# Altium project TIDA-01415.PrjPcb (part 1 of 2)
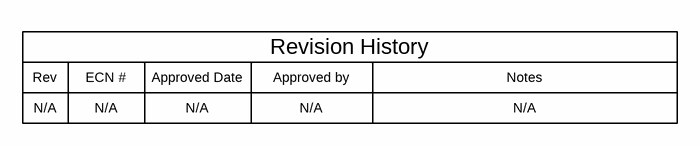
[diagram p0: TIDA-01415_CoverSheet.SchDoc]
CopyrightYear: 2017; EVM Orderable: N/A; PCB_Layout: Kranthi A; PCB_Rev: E1; PRJ_Customer: Public Release; PRJ_Engineer: Surya mishra; PRJ_Number: TIDA-01415; PRJ_Title: High Resolution, high PWM frequency dimmable, color tunable RGBW LED Luminaire; SCH_Rev: E1; TechSupport: http://www.ti.com/support; TID: TIDA-01415
6 sheets, 261 parts. Net scope: flat (ports and power ports of the same name join across sheets).
Board file: TIDA-01415.PcbDoc
Sheets:
  TIDA-01415_CoverSheet.SchDoc
  TIDA-01415_Page1.SchDoc
  TIDA-01415_page3.SchDoc
  TIDA-01415_Page2.SchDoc
  TIDA-01415_page4.SchDoc
  TIDA-01415_EVM_Hardware.SchDoc

## Sheet TIDA-01415_CoverSheet.SchDoc
size 431 x 279 mm; Date: Not shown in title block; ApprovedBy: Not shown in title block; CheckedBy: Not shown in title block; Author: Not shown in title block; CompanyName: Not shown in title block; DrawnBy: Surya Mishra; Engineer: Not shown in title block; Organization: Not shown in title block; Address1: Not shown in title block; Address2: Not shown in title block; Address3: Not shown in title block; Address4: Not shown in title block; DocumentNumber: 1; Revision: Use project parameter SCH_Rev; SheetNumber: 1; SheetTotal: 6; PageSetup: Record=PageOptions¦CenterHorizontal=True¦CenterVertical=True¦PrintScale=1.00¦XCorrection=1.00¦YCorrection=1.00¦PrintKind=0¦BorderSize=5000000¦LeftOffset=0¦BottomOffset=0¦Orientation=2¦PaperLength=1000¦PaperWidth=1000¦Scale=100¦PaperSource=15¦PrintQuality=600¦MediaType=1¦DitherType=10¦PaperKind=Letter¦PrintScaleMode=1

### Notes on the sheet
- Rev
- N/A
- ECN #
- Approved Date
- Approved by
- Revision History
- Notes

## Sheet TIDA-01415_Page1.SchDoc
size 431 x 279 mm; Date: Not shown in title block; ApprovedBy: Not shown in title block; CheckedBy: Not shown in title block; Author: Not shown in title block; CompanyName: Not shown in title block; DrawnBy: Surya Mishra; Engineer: Not shown in title block; Organization: Not shown in title block; Address1: Not shown in title block; Address2: Not shown in title block; Address3: Not shown in title block; Address4: Not shown in title block; DocumentNumber: 1; Revision: Use project parameter SCH_Rev; SheetNumber: 2; SheetTotal: 6; PageSetup: Record=PageOptions¦CenterHorizontal=True¦CenterVertical=True¦PrintScale=1.00¦XCorrection=1.00¦YCorrection=1.00¦PrintKind=0¦BorderSize=5000000¦LeftOffset=0¦BottomOffset=0¦Orientation=2¦PaperLength=1000¦PaperWidth=1000¦Scale=100¦PaperSource=15¦PrintQuality=600¦MediaType=1¦DitherType=10¦PaperKind=Letter¦PrintScaleMode=1
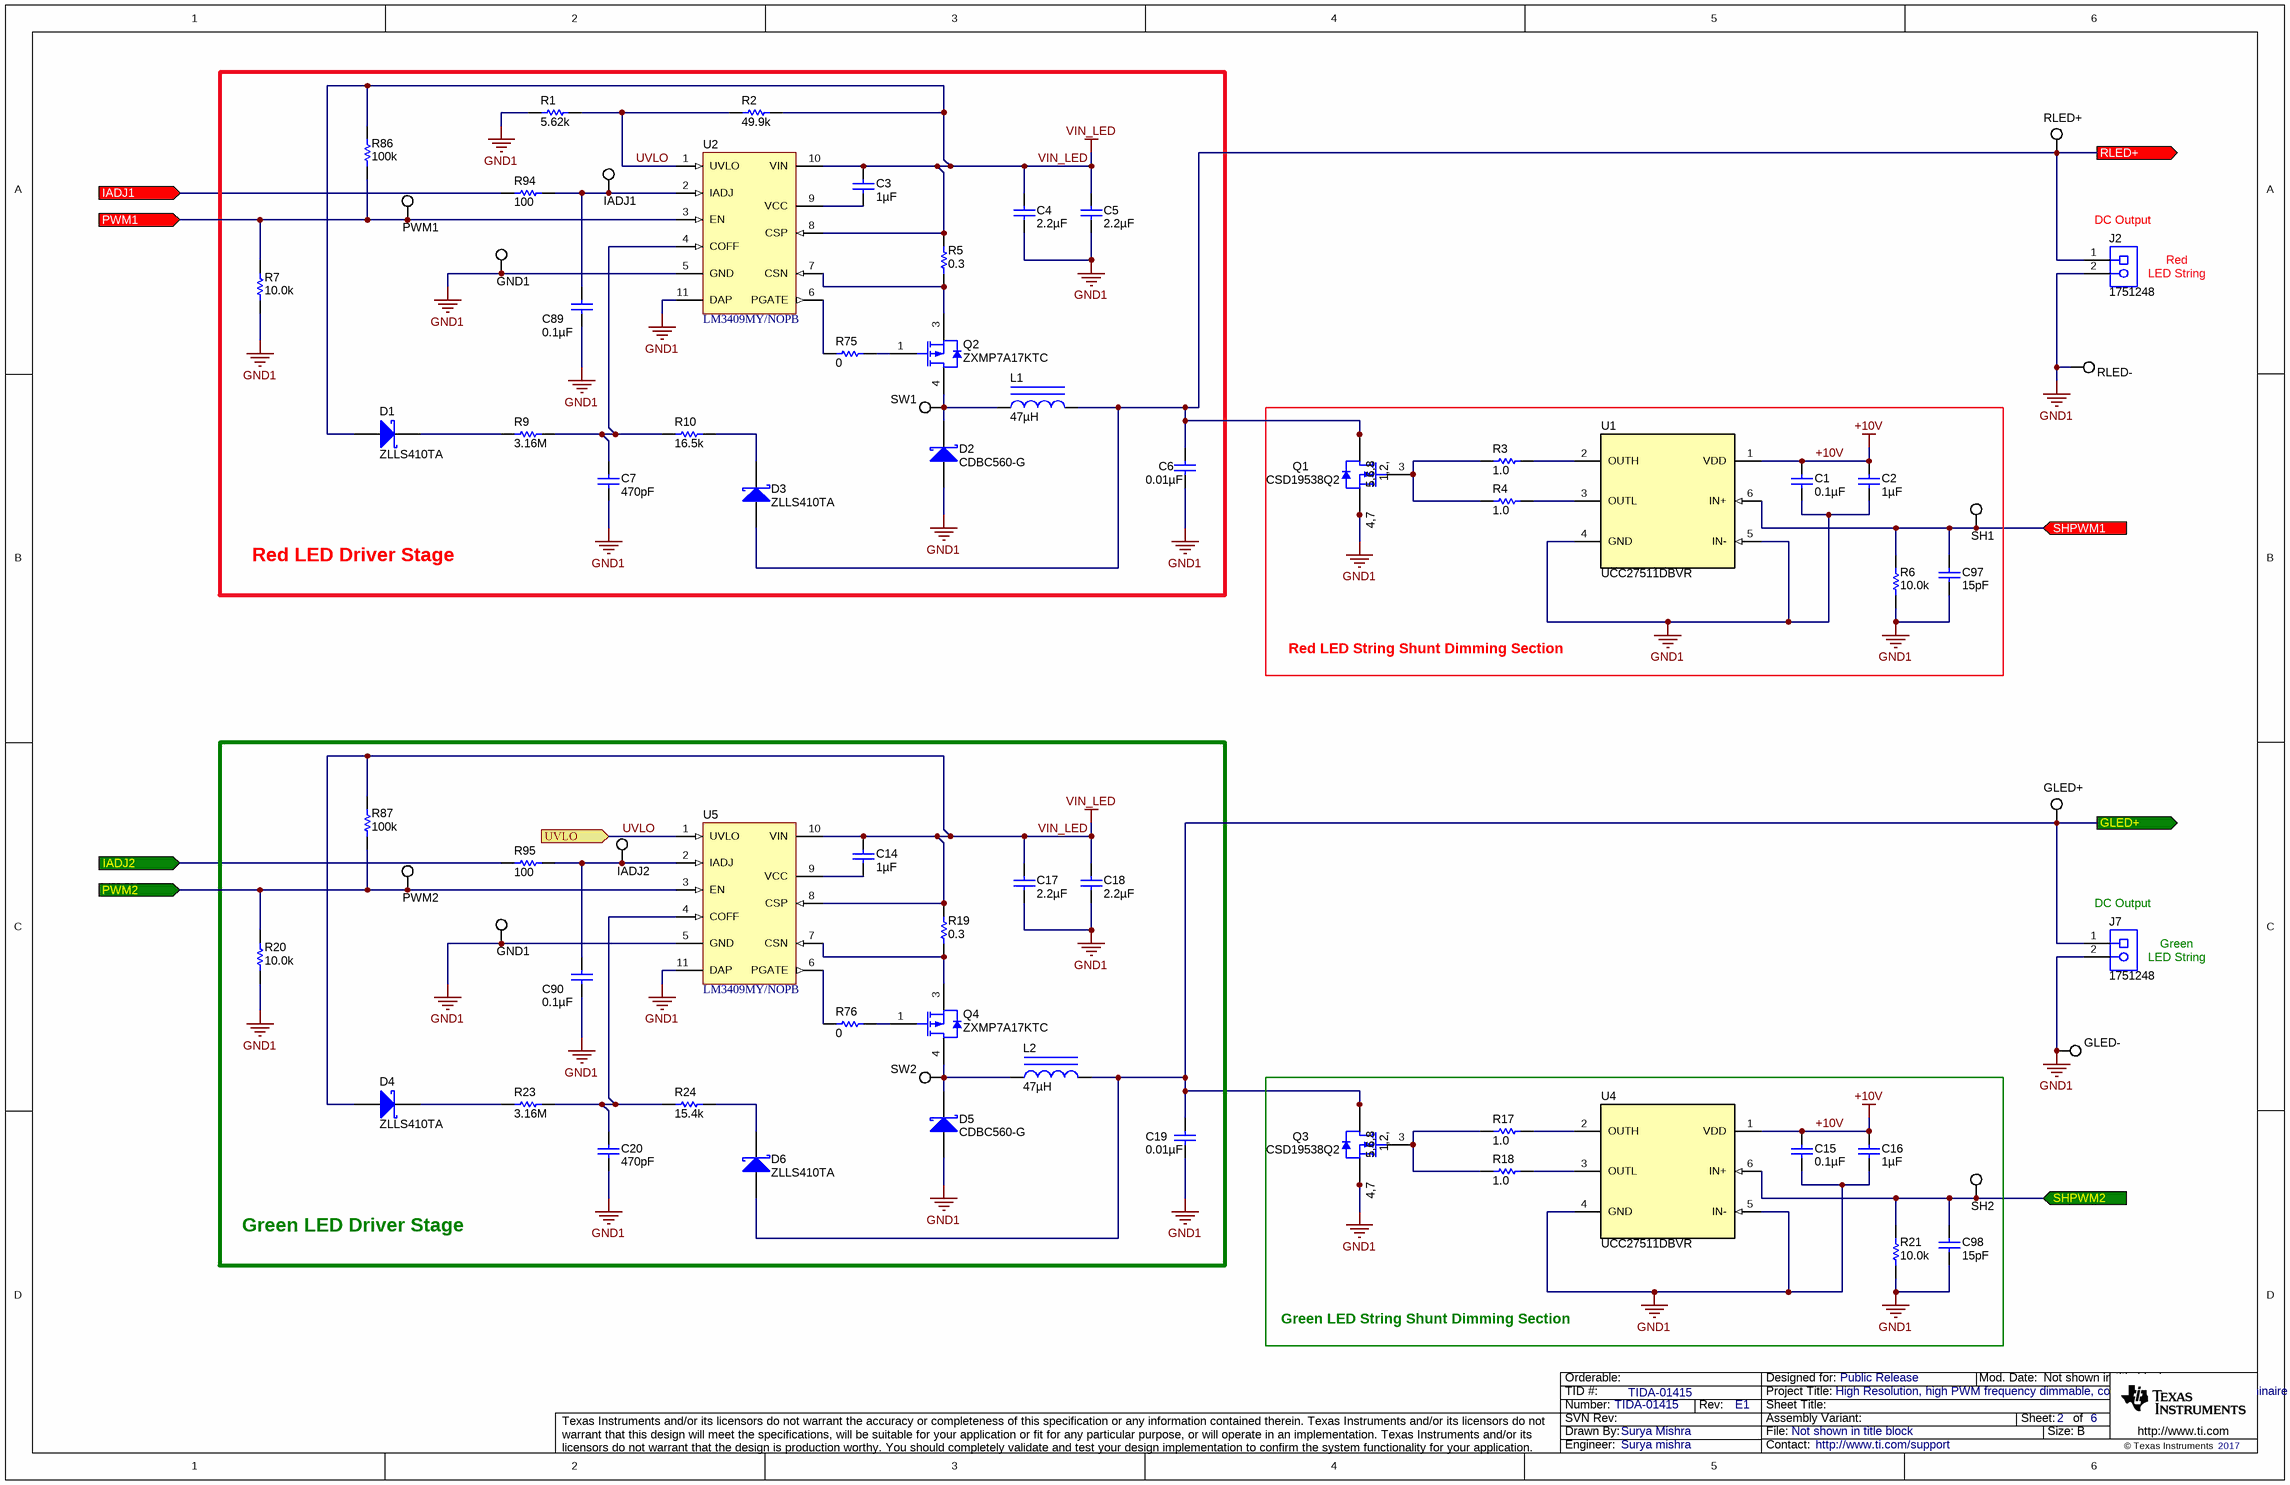
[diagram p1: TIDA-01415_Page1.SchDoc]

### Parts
(Parts that share a designator on the sheet are numbered #1, #2 ... from top to bottom, then left to right.)
C1  ValueDisplayed: 0.1µF  [0805_HV]  (hidden comment: C2012X7R1H104K085AA)
C2  ValueDisplayed: 1µF  [0805_HV]  (hidden comment: C2012X7R1H105K125AB)
C3  ValueDisplayed: 1µF  [0603]  (hidden comment: C1608X7R1C105K080AC)
C4  ValueDisplayed: 2.2µF  [0805_HV]  (hidden comment: C2012X7R1H225K125AC)
C5  ValueDisplayed: 2.2µF  [0805_HV]  (hidden comment: C2012X7R1H225K125AC)
C6  ValueDisplayed: 0.01µF  [0805_HV]  (hidden comment: 885012207092)
C7  ValueDisplayed: 470pF  [0201_033]  (hidden comment: CGA1A2X7R1H471K030BA)
C14  ValueDisplayed: 1µF  [0603]  (hidden comment: C1608X7R1C105K080AC)
C15  ValueDisplayed: 0.1µF  [0805_HV]  (hidden comment: C2012X7R1H104K085AA)
C16  ValueDisplayed: 1µF  [0805_HV]  (hidden comment: C2012X7R1H105K125AB)
C17  ValueDisplayed: 2.2µF  [0805_HV]  (hidden comment: C2012X7R1H225K125AC)
C18  ValueDisplayed: 2.2µF  [0805_HV]  (hidden comment: C2012X7R1H225K125AC)
C19  ValueDisplayed: 0.01µF  [0805_HV]  (hidden comment: 885012207092)
C20  ValueDisplayed: 470pF  [0201_033]  (hidden comment: CGA1A2X7R1H471K030BA)
C89  ValueDisplayed: 0.1µF  [0402]  (hidden comment: C1005X7R1E104M050BB)
C90  ValueDisplayed: 0.1µF  [0402]  (hidden comment: C1005X7R1E104M050BB)
C97  ValueDisplayed: 15pF  [0402]  (hidden comment: 885012005056)
C98  ValueDisplayed: 15pF  [0402]  (hidden comment: 885012005056)
D1  ZLLS410TA  [SOD-323]
D2  CDBC560-G  [SMC]
D3  ZLLS410TA  [SOD-323]
D4  ZLLS410TA  [SOD-323]
D5  CDBC560-G  [SMC]
D6  ZLLS410TA  [SOD-323]
GLED+  5015  [Testpoint_Keystone_Miniature]  (value not drawn)
GLED-  5015  [Testpoint_Keystone_Miniature]  (value not drawn)
GND1#1  5015  [Testpoint_Keystone_Miniature]  (value not drawn)
GND1#2  5015  [Testpoint_Keystone_Miniature]  (value not drawn)
IADJ1  5015  [Testpoint_Keystone_Miniature]  (value not drawn)
IADJ2  5015  [Testpoint_Keystone_Miniature]  (value not drawn)
J2  1751248  [CONN_1751248]
J7  1751248  [CONN_1751248]
L1  ValueDisplayed: 47µH  [WE-PD_1280]  (hidden comment: 744770147)
L2  ValueDisplayed: 47µH  [WE-PD_1280]  (hidden comment: 744770147)
PWM1  5015  [Testpoint_Keystone_Miniature]  (value not drawn)
PWM2  5015  [Testpoint_Keystone_Miniature]  (value not drawn)
Q1  CSD19538Q2  [DQK0006C]
Q2  ZXMP7A17KTC  [DPAK]
Q3  CSD19538Q2  [DQK0006C]
Q4  ZXMP7A17KTC  [DPAK]
R1  ValueDisplayed: 5.62k  [0603]  (hidden comment: CRCW06035K62FKEA)
R2  ValueDisplayed: 49.9k  [0603]  (hidden comment: CRCW060349K9FKEA)
R3  ValueDisplayed: 1.0  [0603]  (hidden comment: CRCW06031R00JNEA)
R4  ValueDisplayed: 1.0  [0603]  (hidden comment: CRCW06031R00JNEA)
R5  ValueDisplayed: 0.3  [2512]  (hidden comment: CSRN2512FKR300)
R6  ValueDisplayed: 10.0k  [0603]  (hidden comment: CRCW060310K0FKEA)
R7  ValueDisplayed: 10.0k  [0603]  (hidden comment: CRCW060310K0FKEA)
R9  ValueDisplayed: 3.16M  [0603]  (hidden comment: CRCW06033M16FKEA)
R10  ValueDisplayed: 16.5k  [0603]  (hidden comment: CRCW060316K5FKEA)
R17  ValueDisplayed: 1.0  [0603]  (hidden comment: CRCW06031R00JNEA)
R18  ValueDisplayed: 1.0  [0603]  (hidden comment: CRCW06031R00JNEA)
R19  ValueDisplayed: 0.3  [2512]  (hidden comment: CSRN2512FKR300)
R20  ValueDisplayed: 10.0k  [0603]  (hidden comment: CRCW060310K0FKEA)
R21  ValueDisplayed: 10.0k  [0603]  (hidden comment: CRCW060310K0FKEA)
R23  ValueDisplayed: 3.16M  [0603]  (hidden comment: CRCW06033M16FKEA)
R24  ValueDisplayed: 15.4k  [0603]  (hidden comment: CRCW060315K4FKEA)
R75  ValueDisplayed: 0  [0603]  (hidden comment: CRCW06030000Z0EA)
R76  ValueDisplayed: 0  [0603]  (hidden comment: CRCW06030000Z0EA)
R86  ValueDisplayed: 100k  [0603]  (hidden comment: CRCW0603100KFKEA)
R87  ValueDisplayed: 100k  [0603]  (hidden comment: CRCW0603100KFKEA)
R94  ValueDisplayed: 100  [0603]  (hidden comment: RC0603FR-07100RL)
R95  ValueDisplayed: 100  [0603]  (hidden comment: RC0603FR-07100RL)
RLED+  5015  [Testpoint_Keystone_Miniature]  (value not drawn)
RLED-  5015  [Testpoint_Keystone_Miniature]  (value not drawn)
SH1  5015  [Testpoint_Keystone_Miniature]  (value not drawn)
SH2  5015  [Testpoint_Keystone_Miniature]  (value not drawn)
SW1  5015  [Testpoint_Keystone_Miniature]  (value not drawn)
SW2  5015  [Testpoint_Keystone_Miniature]  (value not drawn)
U1  UCC27511DBVR  [DBV0006A_N]
U2  LM3409MY/NOPB  [MUC10A_N]
U4  UCC27511DBVR  [DBV0006A_N]
U5  LM3409MY/NOPB  [MUC10A_N]

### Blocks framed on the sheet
Red LED Driver Stage: C3-C7 C89 D1-D3 GND1#1 IADJ1 L1 PWM1 Q2 R1 R2 R5 R7 R9 R10 R75 R86 R94 SW1 U2
Red LED String Shunt Dimming Section: C1 C2 C97 Q1 R3 R4 R6 SH1 U1
Green LED Driver Stage: C14 C17-C20 C90 D4-D6 GND1#2 IADJ2 L2 PWM2 Q4 R19 R20 R23 R24 R76 R87 R95 SW2 U5
Green LED String Shunt Dimming Section: C15 C16 C98 Q3 R17 R18 R21 SH2 U4

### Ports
GLED+ (out), IADJ1 (in), IADJ2 (in), PWM1 (in), PWM2 (in), RLED+ (out), SHPWM1 (in), SHPWM2 (in), UVLO (in)

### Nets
+10V: C1.1 C2.1 C15.1 C16.1 U1.1(VDD) U4.1(VDD)
GND1: C1.2 C2.2 C4.2 C5.2 C6.2 C7.2 C15.2 C16.2 C17.2 C18.2 C19.2 C20.2 C89.1 C90.1 C97.2 C98.2 D2.2(A) D5.2(A) GLED-.1 GND1#1.1 GND1#2.1 J2.2 J7.2 Q1.4(S) Q1.7(S) Q3.4(S) Q3.7(S) R1.1 R6.1 R7.1 R20.1 R21.1 RLED-.1 U1.4(GND) U1.5(IN-) U2.5(GND) U2.11(DAP) U4.4(GND) U4.5(IN-) U5.5(GND) U5.11(DAP)
VIN_LED: C3.1 C4.1 C5.1 C14.1 C17.1 C18.1 D1.2(A) D4.2(A) R2.1 R5.2 R19.2 R86.2 R87.2 U2.8(CSP) U2.10(VIN) U5.8(CSP) U5.10(VIN)
GLED+: C19.1 D6.2(A) GLED+.1 J7.1 L2.2 Q3.1(D) Q3.2(D) Q3.5(D) Q3.6(D) Q3.8(D) ; port GLED+
IADJ1: R94.2 ; port IADJ1
IADJ2: R95.2 ; port IADJ2
PWM1: PWM1.1 R7.2 R86.1 U2.3(EN) ; port PWM1
PWM2: PWM2.1 R20.2 R87.1 U5.3(EN) ; port PWM2
RLED+: C6.1 D3.2(A) J2.1 L1.2 Q1.1(D) Q1.2(D) Q1.5(D) Q1.6(D) Q1.8(D) RLED+.1 ; port RLED+
SHPWM1: C97.1 R6.2 SH1.1 U1.6(IN+) ; port SHPWM1
SHPWM2: C98.1 R21.2 SH2.1 U4.6(IN+) ; port SHPWM2
UVLO: R1.2 R2.2 U2.1(UVLO) U5.1(UVLO) ; port UVLO
NetC3_2: C3.2 U2.9(VCC)
NetC7_1: C7.1 R9.2 R10.1 U2.4(COFF)
NetC14_2: C14.2 U5.9(VCC)
NetC20_1: C20.1 R23.2 R24.1 U5.4(COFF)
NetC89_2: C89.2 IADJ1.1 R94.1 U2.2(IADJ)
NetC90_2: C90.2 IADJ2.1 R95.1 U5.2(IADJ)
NetD1_1: D1.1(K) R9.1
NetD2_1: D2.1(K) L1.1 Q2.4(D) SW1.1
NetD3_1: D3.1(K) R10.2
NetD4_1: D4.1(K) R23.1
NetD5_1: D5.1(K) L2.1 Q4.4(D) SW2.1
NetD6_1: D6.1(K) R24.2
NetQ1_3: Q1.3(G) R3.1 R4.1
NetQ2_1: Q2.1(G) R75.2
NetQ2_3: Q2.3(S) R5.1 U2.7(CSN)
NetQ3_3: Q3.3(G) R17.1 R18.1
NetQ4_1: Q4.1(G) R76.2
NetQ4_3: Q4.3(S) R19.1 U5.7(CSN)
NetR3_2: R3.2 U1.2(OUTH)
NetR4_2: R4.2 U1.3(OUTL)
NetR17_2: R17.2 U4.2(OUTH)
NetR18_2: R18.2 U4.3(OUTL)
NetR75_1: R75.1 U2.6(PGATE)
NetR76_1: R76.1 U5.6(PGATE)

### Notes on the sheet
- (near J2) DC Output
- Red
- (near J2) LED String
- (near J7) DC Output
- (near J7) Green
- (near J7) LED String

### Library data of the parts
C1 C15 = C2012X7R1H104K085AA: CAP, CERM, 0.1 µF, 50 V, +/- 10%, X7R, 0805; Manufacturer: TDK; Polarized: N; CompType: Capacitor; Value: 0.1uF; U/M: EA; Cap_F: 0.0000001; Tolerance_%: 10; ESR_ohm: 0.02619; Value1: 0.02619 ohm; VDC_V: 50; Value2: 50V; IRMS_A: 1.29514; TaMin_C: -55; TaMax_C: 125; Cap_Case: 0805; SizeArea_mm2: 2.5; SizeAreaWB_mm2: 6.75; SizeX_mm: 2; SizeY_mm: 1.25; SizeZ_mm: 1.45; AEC Category: Q200
C2 C16 = C2012X7R1H105K125AB: CAP, CERM, 1 µF, 50 V, +/- 10%, X7R, 0805; Manufacturer: TDK; Polarized: N; CompType: Capacitor; Value: 1uF; U/M: EA; Cap_F: 0.000001; Tolerance_%: 10; ESR_ohm: 0.008782; Value1: 0.008782 ohm; VDC_V: 50; Value2: 50V; IRMS_A: 2.20488; TaMin_C: -55; TaMax_C: 125; Cap_Case: 0805; SizeArea_mm2: 2.5; SizeAreaWB_mm2: 6.75; SizeX_mm: 2; SizeY_mm: 1.25; SizeZ_mm: 1.45; AEC Category: Q200
C3 C14 = C1608X7R1C105K080AC: CAP, CERM, 1 µF, 16 V, +/- 10%, X7R, 0603; Manufacturer: TDK; Polarized: N; CompType: Capacitor; Value: 1uF; U/M: EA; Cap_F: 0.000001; Tolerance_%: 10; ESR_ohm: 0.0057; Value1: 0.0057 ohm; VDC_V: 16; Value2: 16V; TaMin_C: -55; TaMax_C: 125; SizeArea_mm2: 1.28; SizeAreaWB_mm2: 4.68; SizeX_mm: 1.6; SizeY_mm: 0.8; SizeZ_mm: 1; AEC Category: Q200
C4 C5 C17 C18 = C2012X7R1H225K125AC: CAP, CERM, 2.2 µF, 50 V, +/- 10%, X7R, 0805; Manufacturer: TDK; Polarized: N; CompType: Capacitor; Value: 2.2uF; U/M: EA; Cap_F: 0.0000022; Tolerance_%: 10; ESR_ohm: 0.00366; Value1: 0.00366 ohm; VDC_V: 50; Value2: 50V; IRMS_A: 3.41207; TaMin_C: -55; TaMax_C: 125; Cap_Case: 0805; SizeArea_mm2: 2.5; SizeAreaWB_mm2: 6.75; SizeX_mm: 2; SizeY_mm: 1.25; SizeZ_mm: 1.45; AEC Category: Q200
C6 C19 = 885012207092: CAP, CERM, 0.01 µF, 50 V, +/- 10%, X7R, 0805; Manufacturer: Wurth Elektronik; Polarized: N; CompType: Capacitor; Value: 0.01uF; U/M: EA; Cap_F: 0.00000001; Tolerance_%: 10; Value1: Unknown; VDC_V: 50; Value2: 50V; TaMin_C: -55; TaMax_C: 125; Cap_Case: 0805; SizeArea_mm2: 2.5; SizeAreaWB_mm2: 6.75; SizeX_mm: 2; SizeY_mm: 1.25; SizeZ_mm: 1.45; AEC Category: Q200
C7 C20 = CGA1A2X7R1H471K030BA: CAP, CERM, 470 pF, 50 V, +/- 10%, X7R, AEC-Q200 Grade 1, 0201; Manufacturer: TDK; Polarized: N; CompType: Capacitor; Value: 470pF; U/M: EA; Cap_F: 0.00000000047; Tolerance_%: 10; ESR_ohm: 5.54785; Value1: 5.54785 ohm; VDC_V: 50; Value2: 50V; IRMS_A: 0.228855; TaMin_C: -55; TaMax_C: 125; SizeArea_mm2: 0.18; SizeAreaWB_mm2: 2.08; SizeX_mm: 0.6; SizeY_mm: 0.3; SizeZ_mm: 0.33; AEC Category: Q200; AEC Qualified: Y; AEC Grade: 1
C89 C90 = C1005X7R1E104M050BB: CAP, CERM, 0.1 µF, 25 V, +/- 20%, X7R, 0402; Manufacturer: TDK; Polarized: N; CompType: Capacitor; Value: 0.1uF; U/M: EA; Cap_F: 0.0000001; Tolerance_%: 20; Value1: Unknown; VDC_V: 25; Value2: 25V; TaMin_C: -55; TaMax_C: 125; SizeArea_mm2: 0.5; SizeAreaWB_mm2: 3; SizeX_mm: 1; SizeZ_mm: 0.6; AEC Category: Q200
C97 C98 = 885012005056: CAP, CERM, 15 pF, 50 V, +/- 5%, C0G/NP0, 0402; Manufacturer: Wurth Elektronik; Polarized: N; CompType: Capacitor; Value: 15pF; U/M: EA; Cap_F: 0.000000000015; Tolerance_%: 5; Value1: Unknown; VDC_V: 50; Value2: 50V; TaMin_C: -55; TaMax_C: 125; SizeArea_mm2: 0.5; SizeAreaWB_mm2: 3; SizeX_mm: 1; SizeZ_mm: 0.6; AEC Category: Q200
D1 D3 D4 D6 = ZLLS410TA: Diode, Schottky, 10 V, 0.75 A, SOD-323; Manufacturer: Diodes Inc.; U/M: EA; Value: 10V; Value1: 0.75A; Io_A: 0.75; Vr_V: 10; TJmax_C: 150; SizeAreaWB_mm2: 8.695; SizeArea_mm2: 3.645; SizeX_mm: 2.7; SizeY_mm: 1.35; SizeZ_mm: 1; AEC Category: Q101; AEC Qualified: N
D2 D5 = CDBC560-G: Diode, Schottky, 60 V, 5 A, SMC; Manufacturer: Comchip Technology; U/M: EA; Vf_V: 0.75; Value: 60V; Value1: 5A; Value2: 0.75V; Io_A: 5; Vr_V: 60; TJmax_C: 125; SizeAreaWB_mm2: 83.2686; SizeArea_mm2: 50.5686; SizeX_mm: 8.13; SizeY_mm: 6.22; SizeZ_mm: 2.6; AEC Category: Q101
GLED+ GLED- GND1#1 GND1#2 IADJ1 IADJ2 PWM1 PWM2 RLED+ RLED- SH1 SH2 SW1 SW2 = 5015: Test Point, Miniature, SMT; Manufacturer: Keystone; CompType: Test Point Loop
J2 J7 = 1751248: Conn Term Block, 2POS, 3.5mm, TH; Manufacturer: Phoenix Contact; SymbolCreator: a0412235; CompType: Terminal Block
L1 L2 = 744770147: Inductor, Shielded Drum Core, Ferrite, 47 µH, 2.7 A, 0.076 ohm, SMD; Manufacturer: Wurth Elektronik; Value: 47uH; Ind_H: 47.0E-6; Imax_A: 2.7; Irms: 2.7A @ 40C rise; Isat: 3A @ 10% inductance drop; DCR_ohm: 0.076; Value2: 2.7A; SizeAreaWB_mm2: 196; SizeArea_mm2: 144; SizeX_mm: 12; SizeZ_mm: 8; AEC Category: Q200
Q1 Q3 = CSD19538Q2: MOSFET, N-CH, 100 V, 4.5 A, DQK0006C (WSON-6); Manufacturer: Texas Instruments; Alternate Manufacturer: None; U/M: EA; ChType: N; Value: 100V; VdsMax_V: 100; Value1: ? ohm; Value2: ? nC; Vgs_V: 20; IdsMax_A: 4.5; SizeAreaWB_mm2: 9; SizeArea_mm2: 4; SizeX_mm: 2; SizeZ_mm: 0.8; AEC Category: Q101
Q2 Q4 = ZXMP7A17KTC: MOSFET, P-CH, -70 V, -5.7 A, DPAK; Manufacturer: Diodes Inc.; Alternate Manufacturer: None; U/M: EA; ChType: P; Value: -70V; Value1: 0.25 ohm; Rdson45_ohm: 0.25; Value2: 18 nC; QgTyp_nC: 18; Vgs_V: -20; SizeAreaWB_mm2: 101.7114; SizeArea_mm2: 64.8114; SizeX_mm: 9.91; SizeY_mm: 6.54; SizeZ_mm: 2.29; AEC Category: Q101; AEC Qualified: N
R1 = CRCW06035K62FKEA: RES, 5.62 k, 1%, 0.1 W, 0603; Manufacturer: Vishay-Dale; CompType: Resistor; Value: 5.62k; Res_ohm: 5620; Value_Code: 5k62; Tolerance_%: 1; Power_W: 0.1; Value2: 0.1W; VDC_V: 75; TempCo: 100 ppm/C; SizeArea_mm2: 1.28; SizeX_mm: 1.6; SizeY_mm: 0.8; EIA_Code: E96; U/M: EA; AEC Category: Q200
R2 = CRCW060349K9FKEA: RES, 49.9 k, 1%, 0.1 W, 0603; Manufacturer: Vishay-Dale; CompType: Resistor; Value: 49.9k; Res_ohm: 49900; Value_Code: 49k9; Tolerance_%: 1; Power_W: 0.1; Value2: 0.1W; VDC_V: 75; TempCo: 100 ppm/C; SizeArea_mm2: 1.28; SizeX_mm: 1.6; SizeY_mm: 0.8; EIA_Code: E96; U/M: EA; AEC Category: Q200
R3 R4 R17 R18 = CRCW06031R00JNEA: RES, 1.0, 5%, 0.1 W, 0603; Manufacturer: Vishay-Dale; CompType: Resistor; Value: 1.0; Res_ohm: 1; Value_Code: 1R00; Tolerance_%: 5; Power_W: 0.1; Value2: 0.1W; VDC_V: 75; TempCo: 200 ppm/C; SizeArea_mm2: 1.28; SizeX_mm: 1.6; SizeY_mm: 0.8; EIA_Code: E24; U/M: EA; AEC Category: Q200
R5 R19 = CSRN2512FKR300: RES, 0.3, 1%, 2 W, 2512; Manufacturer: Stackpole Electronics Inc; CompType: Resistor; Value: 0.3; Value_Code: R300; Tolerance_%: 1; Power_W: 2; Value2: 2W; TempCo: 200 ppm/C; SizeArea_mm2: 20.16; SizeX_mm: 6.3; SizeY_mm: 3.2; SizeZ_mm: 0.71; EIA_Code: E96; U/M: EA; AEC Category: Q200
R6 R7 R20 R21 = CRCW060310K0FKEA: RES, 10.0 k, 1%, 0.1 W, 0603; Manufacturer: Vishay-Dale; CompType: Resistor; Value: 10.0k; Res_ohm: 10000; Value_Code: 10k0; Tolerance_%: 1; Power_W: 0.1; Value2: 0.1W; VDC_V: 75; TempCo: 100 ppm/C; SizeArea_mm2: 1.28; SizeX_mm: 1.6; SizeY_mm: 0.8; EIA_Code: E96; U/M: EA; AEC Category: Q200
R9 R23 = CRCW06033M16FKEA: RES, 3.16 M, 1%, 0.1 W, 0603; Manufacturer: Vishay-Dale; CompType: Resistor; Value: 3.16Meg; Res_ohm: 3160000; Value_Code: 3M16; Tolerance_%: 1; Power_W: 0.1; Value2: 0.1W; VDC_V: 75; TempCo: 100 ppm/C; SizeArea_mm2: 1.28; SizeX_mm: 1.6; SizeY_mm: 0.8; EIA_Code: E96; U/M: EA; AEC Category: Q200
R10 = CRCW060316K5FKEA: RES, 16.5 k, 1%, 0.1 W, 0603; Manufacturer: Vishay-Dale; CompType: Resistor; Value: 16.5k; Res_ohm: 16500; Value_Code: 16k5; Tolerance_%: 1; Power_W: 0.1; Value2: 0.1W; VDC_V: 75; TempCo: 100 ppm/C; SizeArea_mm2: 1.28; SizeX_mm: 1.6; SizeY_mm: 0.8; EIA_Code: E96; U/M: EA; AEC Category: Q200
R24 = CRCW060315K4FKEA: RES, 15.4 k, 1%, 0.1 W, 0603; Manufacturer: Vishay-Dale; CompType: Resistor; Value: 15.4k; Res_ohm: 15400; Value_Code: 15k4; Tolerance_%: 1; Power_W: 0.1; Value2: 0.1W; VDC_V: 75; TempCo: 100 ppm/C; SizeArea_mm2: 1.28; SizeX_mm: 1.6; SizeY_mm: 0.8; EIA_Code: E96; U/M: EA; AEC Category: Q200
R75 R76 = CRCW06030000Z0EA: RES, 0, 5%, 0.1 W, 0603; Manufacturer: Vishay-Dale; CompType: Resistor; Value: 0; Value_Code: 0000; Tolerance_%: 5; Power_W: 0.1; Value2: 0.1W; VDC_V: 75; TempCo: 200 ppm/C; SizeArea_mm2: 1.28; SizeX_mm: 1.6; SizeY_mm: 0.8; SizeZ_mm: 1; EIA_Code: E24; U/M: EA; AEC Category: Q200
R86 R87 = CRCW0603100KFKEA: RES, 100 k, 1%, 0.1 W, 0603; Manufacturer: Vishay-Dale; CompType: Resistor; Value: 100k; Res_ohm: 100000; Tolerance_%: 1; Power_W: 0.1; Value2: 0.1W; VDC_V: 75; TempCo: 100 ppm/C; SizeArea_mm2: 1.28; SizeX_mm: 1.6; SizeY_mm: 0.8; EIA_Code: E96; U/M: EA; AEC Category: Q200
R94 R95 = RC0603FR-07100RL: RES, 100, 1%, 0.1 W, 0603; Manufacturer: Yageo America; CompType: Resistor; Value: 100; Value_Code: 100R; Tolerance_%: 1; Power_W: 0.1; Value2: 0.1W; VDC_V: 150; TempCo: 200 ppm/C; SizeArea_mm2: 1.28; SizeX_mm: 1.6; SizeY_mm: 0.8; EIA_Code: E96; U/M: EA; AEC Category: Q200
U1 U4 = UCC27511DBVR: Single-Channel High-Speed Low-Side Gate Driver (with 4-A Peak Source and 8-A Peak Sink), DBV0006A (SOT-6); Alternate PartNumber: UCC27511DBVT; Manufacturer: Texas Instruments; SymbolCreator: a0411947; SizeArea_mm2: 8.12; SizeAreaWB_mm2: 14.82; SizeX_mm: 2.8; SizeY_mm: 2.9; SizeZ_mm: 1.45; CompType: IC; U/M: EA
U2 U5 = LM3409MY/NOPB: PFET Buck Controller for High Power LED Drives, 10-pin eMSOP, Pb-Free; Manufacturer: Texas Instruments; PackageTopMarking: ZXTT*SXFB; PowerWise: Y; CompType: MiscPower

## Sheet TIDA-01415_page3.SchDoc
size 431 x 279 mm; Date: Not shown in title block; ApprovedBy: Not shown in title block; CheckedBy: Not shown in title block; Author: Not shown in title block; CompanyName: Not shown in title block; DrawnBy: Surya Mishra; Engineer: Not shown in title block; Organization: Not shown in title block; Address1: Not shown in title block; Address2: Not shown in title block; Address3: Not shown in title block; Address4: Not shown in title block; DocumentNumber: 1; Revision: Use project parameter SCH_Rev; SheetNumber: 4; SheetTotal: 6; PageSetup: Record=PageOptions¦CenterHorizontal=True¦CenterVertical=True¦PrintScale=1.00¦XCorrection=1.00¦YCorrection=1.00¦PrintKind=0¦BorderSize=5000000¦LeftOffset=0¦BottomOffset=0¦Orientation=2¦PaperLength=1000¦PaperWidth=1000¦Scale=100¦PaperSource=15¦PrintQuality=600¦MediaType=1¦DitherType=10¦PaperKind=Letter¦PrintScaleMode=1
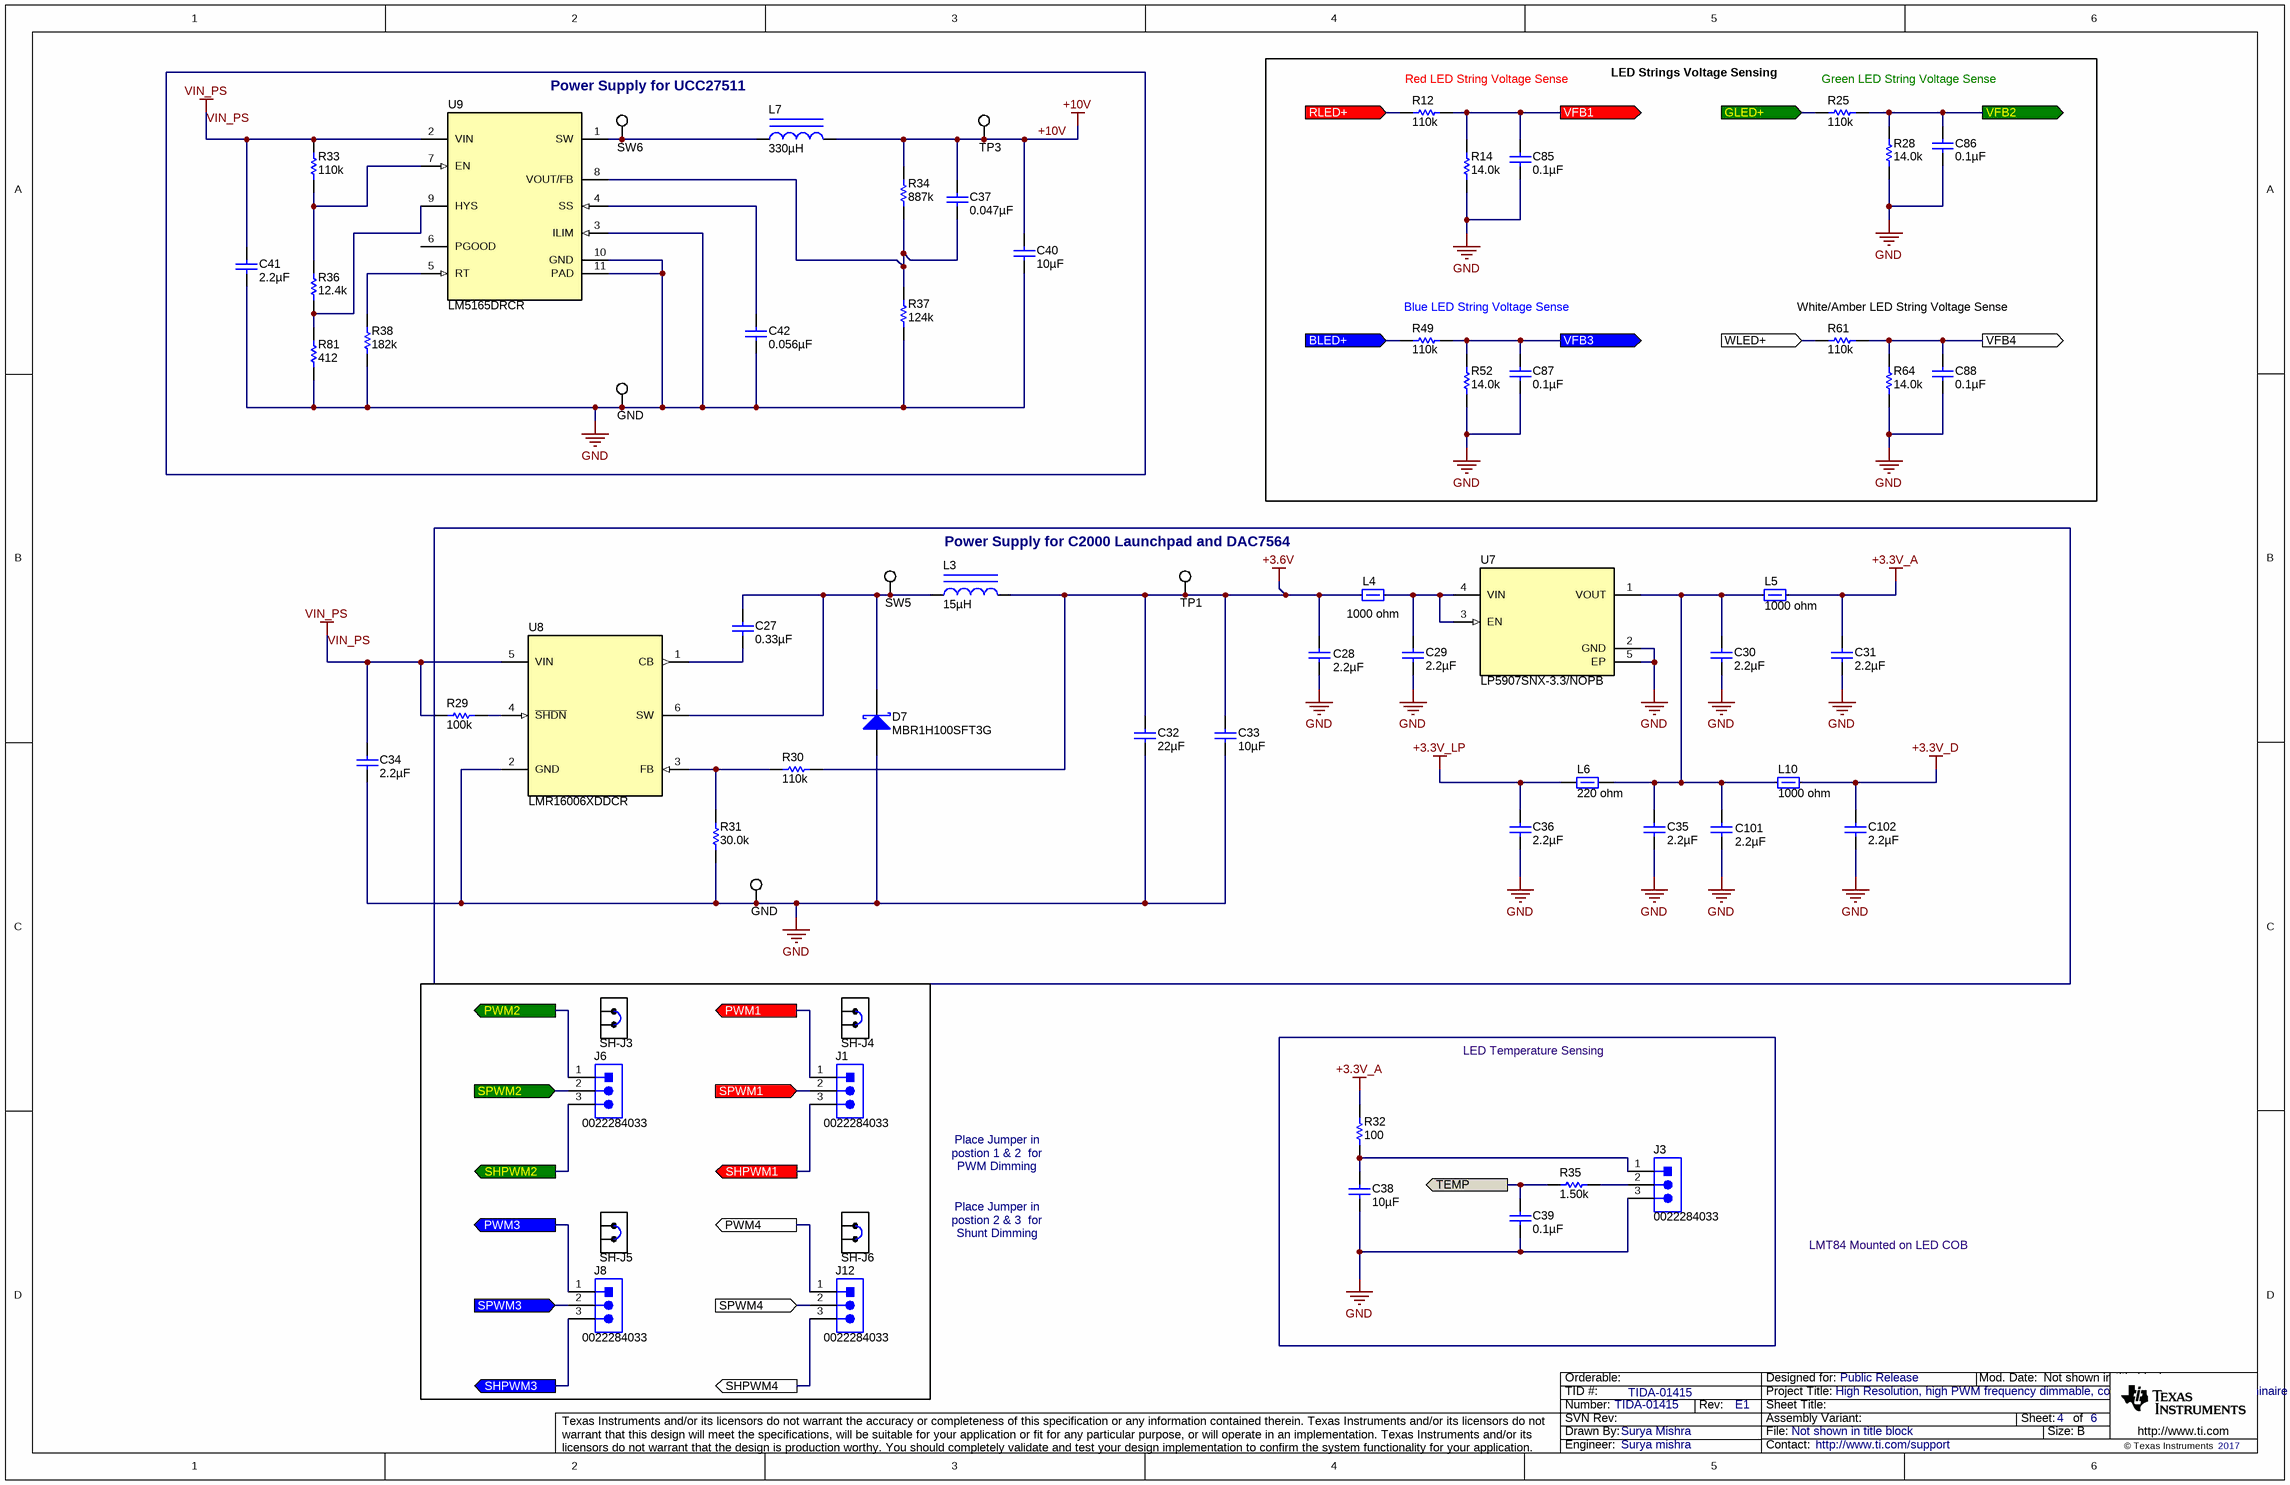
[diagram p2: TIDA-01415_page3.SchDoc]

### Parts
(Parts that share a designator on the sheet are numbered #1, #2 ... from top to bottom, then left to right.)
C27  ValueDisplayed: 0.33µF  [0603]  (hidden comment: C0603C334K4RACTU)
C28  ValueDisplayed: 2.2µF  [0805_HV]  (hidden comment: C2012X7R1C225K125AB)
C29  ValueDisplayed: 2.2µF  [0805_HV]  (hidden comment: C2012X7R1C225K125AB)
C30  ValueDisplayed: 2.2µF  [0805_HV]  (hidden comment: C2012X7R1C225K125AB)
C31  ValueDisplayed: 2.2µF  [0805_HV]  (hidden comment: C2012X7R1C225K125AB)
C32  ValueDisplayed: 22µF  [1206_180]  (hidden comment: GRM31CR61C226KE15L)
C33  ValueDisplayed: 10µF  [0603]  (hidden comment: GRT188C81A106ME13D)
C34  ValueDisplayed: 2.2µF  [0805_HV]  (hidden comment: C2012X7R1H225K125AC)
C35  ValueDisplayed: 2.2µF  [0805_HV]  (hidden comment: C2012X7R1C225K125AB)
C36  ValueDisplayed: 2.2µF  [0805_HV]  (hidden comment: C2012X7R1C225K125AB)
C37  ValueDisplayed: 0.047µF  [0603]  (hidden comment: GCM188R71E473KA37D)
C38  ValueDisplayed: 10µF  [0603]  (hidden comment: GRT188C81A106ME13D)
C39  ValueDisplayed: 0.1µF  [0603]  (hidden comment: GRM188R71E104KA01D)
C40  ValueDisplayed: 10µF  [0805_HV]  (hidden comment: CGA4J1X7S1C106K125AC)
C41  ValueDisplayed: 2.2µF  [0805_HV]  (hidden comment: C2012X7R1H225K125AC)
C42  ValueDisplayed: 0.056µF  [0402]  (hidden comment: GRM155R71C563KA88D)
C85  ValueDisplayed: 0.1µF  [0805_HV]  (hidden comment: C2012X7R1H104K085AA)
C86  ValueDisplayed: 0.1µF  [0805_HV]  (hidden comment: C2012X7R1H104K085AA)
C87  ValueDisplayed: 0.1µF  [0805_HV]  (hidden comment: C2012X7R1H104K085AA)
C88  ValueDisplayed: 0.1µF  [0805_HV]  (hidden comment: C2012X7R1H104K085AA)
C101  ValueDisplayed: 2.2µF  [0805_HV]  (hidden comment: C2012X7R1C225K125AB)
C102  ValueDisplayed: 2.2µF  [0805_HV]  (hidden comment: C2012X7R1C225K125AB)
D7  MBR1H100SFT3G  [SOD-123FL]
GND#1  5015  [Testpoint_Keystone_Miniature]  (value not drawn)
GND#2  5015  [Testpoint_Keystone_Miniature]  (value not drawn)
J1  0022284033  [Molex_0022284033]
J3  0022284033  [Molex_0022284033]
J6  0022284033  [Molex_0022284033]
J8  0022284033  [Molex_0022284033]
J12  0022284033  [Molex_0022284033]
L3  ValueDisplayed: 15µH  [WE-TPC-LH]  (hidden comment: 744053150)
L4  value 1000 ohm  [0603]  (hidden comment: 742792662)
L5  value 1000 ohm  [0603]  (hidden comment: 742792662)
L6  ValueDisplayed: 220 ohm  [0402]  (hidden comment: BLM15AG221SN1D)
L7  ValueDisplayed: 330µH  [SDR0403]  (hidden comment: SDR0403-331KL)
L10  value 1000 ohm  [0603]  (hidden comment: 742792662)
R12  ValueDisplayed: 110k  [0603]  (hidden comment: CRCW0603110KFKEA)
R14  ValueDisplayed: 14.0k  [0603]  (hidden comment: CRCW060314K0FKEA)
R25  ValueDisplayed: 110k  [0603]  (hidden comment: CRCW0603110KFKEA)
R28  ValueDisplayed: 14.0k  [0603]  (hidden comment: CRCW060314K0FKEA)
R29  ValueDisplayed: 100k  [0603]  (hidden comment: CRCW0603100KFKEA)
R30  ValueDisplayed: 110k  [0603]  (hidden comment: CRCW0603110KFKEA)
R31  ValueDisplayed: 30.0k  [0603]  (hidden comment: RC0603FR-0730KL)
R32  ValueDisplayed: 100  [0603]  (hidden comment: RC0603FR-07100RL)
R33  ValueDisplayed: 110k  [0603]  (hidden comment: CRCW0603110KFKEA)
R34  ValueDisplayed: 887k  [0402]  (hidden comment: CRCW0402887KFKED)
R35  ValueDisplayed: 1.50k  [0603]  (hidden comment: RC0603FR-071K5L)
R36  ValueDisplayed: 12.4k  [0603]  (hidden comment: CRCW060312K4FKEA)
R37  ValueDisplayed: 124k  [0402]  (hidden comment: CRCW0402124KFKED)
R38  ValueDisplayed: 182k  [0402]  (hidden comment: CRCW0402182KFKED)
R49  ValueDisplayed: 110k  [0603]  (hidden comment: CRCW0603110KFKEA)
R52  ValueDisplayed: 14.0k  [0603]  (hidden comment: CRCW060314K0FKEA)
R61  ValueDisplayed: 110k  [0603]  (hidden comment: CRCW0603110KFKEA)
R64  ValueDisplayed: 14.0k  [0603]  (hidden comment: CRCW060314K0FKEA)
R81  ValueDisplayed: 412  [1206]  (hidden comment: CRCW1206412RFKEA)
SH-J3  969102-0000-DA  [SNT-100-BK-G]  (value not drawn)
SH-J4  969102-0000-DA  [SNT-100-BK-G]  (value not drawn)
SH-J5  969102-0000-DA  [SNT-100-BK-G]  (value not drawn)
SH-J6  969102-0000-DA  [SNT-100-BK-G]  (value not drawn)
SW5  5015  [Testpoint_Keystone_Miniature]  (value not drawn)
SW6  5015  [Testpoint_Keystone_Miniature]  (value not drawn)
TP1  5015  [Testpoint_Keystone_Miniature]  (value not drawn)
TP3  5015  [Testpoint_Keystone_Miniature]  (value not drawn)
U7  LP5907SNX-3.3/NOPB  [DQN0004A]
U8  LMR16006XDDCR  [DDC0006A_N]
U9  LM5165DRCR  [DRC0010J]

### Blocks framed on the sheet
Power Supply for UCC27511: C37 C40-C42 GND#1 L7 R33 R34 R36-R38 R81 SW6 TP3 U9
Power Supply for C2000 Launchpad and DAC7564: C27-C33 C35 C36 C101 C102 D7 GND#2 L3-L6 L10 R29-R31 SW5 TP1 U7 U8
LED Temperature Sensing: C38 C39 J3 R32 R35

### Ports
BLED+ (in), GLED+ (in), PWM1 (out), PWM2 (out), PWM3 (out), PWM4 (out), RLED+ (in), SHPWM1 (out), SHPWM2 (out), SHPWM3 (out), SHPWM4 (out), SPWM1 (in), SPWM2 (in), SPWM3 (in), SPWM4 (in), TEMP (out), VFB1 (out), VFB2 (out), VFB3 (out), VFB4 (out), WLED+ (in)

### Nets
+3.3V_A: C31.1 L5.2 R32.2
+3.3V_D: C102.1 L10.2
+3.3V_LP: C36.1 L6.2
+3.6V: C28.1 C32.1 C33.1 L3.2 L4.1 R30.2 TP1.1
+10V: C37.1 C40.1 L7.2 R34.2 TP3.1
GND: C28.2 C29.2 C30.2 C31.2 C32.2 C33.2 C34.2 C35.2 C36.2 C38.2 C39.2 C40.2 C41.2 C42.2 C85.1 C86.1 C87.1 C88.1 C101.2 C102.2 D7.2(A) GND#1.1 GND#2.1 J3.3 R14.1 R28.1 R31.1 R37.1 R38.1 R52.1 R64.1 R81.1 U7.2(GND) U7.5(EP) U8.2(GND) U9.3(ILIM) U9.10(GND) U9.11(PAD)
VIN_PS: C34.1 C41.1 R29.2 R33.2 U8.5(VIN) U9.2(VIN)
BLED+: R49.2 ; port BLED+
GLED+: R25.2 ; port GLED+
PWM1: J1.1 ; port PWM1
PWM2: J6.1 ; port PWM2
PWM3: J8.1 ; port PWM3
PWM4: J12.1 ; port PWM4
RLED+: R12.2 ; port RLED+
SHPWM1: J1.3 ; port SHPWM1
SHPWM2: J6.3 ; port SHPWM2
SHPWM3: J8.3 ; port SHPWM3
SHPWM4: J12.3 ; port SHPWM4
SPWM1: J1.2 ; port SPWM1
SPWM2: J6.2 ; port SPWM2
SPWM3: J8.2 ; port SPWM3
SPWM4: J12.2 ; port SPWM4
TEMP: C39.1 R35.1 ; port TEMP
VFB1: C85.2 R12.1 R14.2 ; port VFB1
VFB2: C86.2 R25.1 R28.2 ; port VFB2
VFB3: C87.2 R49.1 R52.2 ; port VFB3
VFB4: C88.2 R61.1 R64.2 ; port VFB4
WLED+: R61.2 ; port WLED+
NetC27_1: C27.1 D7.1(K) L3.1 SW5.1 U8.6(SW)
NetC27_2: C27.2 U8.1(CB)
NetC29_1: C29.1 L4.2 U7.3(EN) U7.4(VIN)
NetC30_1: C30.1 C35.1 C101.1 L5.1 L6.1 L10.1 U7.1(VOUT)
NetC37_2: C37.2 R34.1 R37.2 U9.8(VOUT/FB)
NetC38_1: C38.1 J3.1 R32.1
NetC42_1: C42.1 U9.4(SS)
NetJ3_2: J3.2 R35.2
NetL7_1: L7.1 SW6.1 U9.1(SW)
NetR29_1: R29.1 U8.4(~{SHDN})
NetR30_1: R30.1 R31.2 U8.3(FB)
NetR33_1: R33.1 R36.2 U9.7(EN)
NetR36_1: R36.1 R81.2 U9.9(HYS)
NetR38_2: R38.2 U9.5(RT)

Not connected (* = marked no-connect by the designer): U9 6(PGOOD)

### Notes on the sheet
- (near R12) Red LED String Voltage Sense
- LED Strings Voltage Sensing
- (near R25) Green LED String Voltage Sense
- (near R49) Blue LED String Voltage Sense
- (near R61) White/Amber LED String Voltage Sense
- Place Jumper in postion 1 & 2  for PWM Dimming
- LMT84 Mounted on LED COB
- Place Jumper in postion 2 & 3  for Shunt Dimming

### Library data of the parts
C27 = C0603C334K4RACTU: CAP, CERM, 0.33 µF, 16 V, +/- 10%, X7R, 0603; Manufacturer: Kemet; Polarized: N; CompType: Capacitor; Value: 0.33uF; U/M: EA; Cap_F: 0.00000033; Tolerance_%: 10; Value1: Unknown; VDC_V: 16; Value2: 16V; TaMin_C: -55; TaMax_C: 125; SizeArea_mm2: 1.28; SizeAreaWB_mm2: 4.68; SizeX_mm: 1.6; SizeY_mm: 0.8; SizeZ_mm: 1; AEC Category: Q200
C28-C31 C35 C36 C101 C102 = C2012X7R1C225K125AB: CAP, CERM, 2.2 µF, 16 V, +/- 10%, X7R, 0805; Manufacturer: TDK; Polarized: N; CompType: Capacitor; Value: 2.2uF; U/M: EA; Cap_F: 0.0000022; Tolerance_%: 10; ESR_ohm: 0.0049; Value1: 0.0049 ohm; VDC_V: 16; Value2: 16V; TaMin_C: -55; TaMax_C: 125; Cap_Case: 0805; SizeArea_mm2: 2.5; SizeAreaWB_mm2: 6.75; SizeX_mm: 2; SizeY_mm: 1.25; SizeZ_mm: 1.45; AEC Category: Q200
C32 = GRM31CR61C226KE15L: CAP, CERM, 22 µF, 16 V, +/- 10%, X5R, 1206; Manufacturer: MuRata; Polarized: N; CompType: Capacitor; Value: 22uF; U/M: EA; Cap_F: 0.000022; Tolerance_%: 10; Value1: Unknown; VDC_V: 16; Value2: 16V; TaMin_C: -55; TaMax_C: 85; Cap_Case: 1206; SizeArea_mm2: 5.12; SizeAreaWB_mm2: 10.92; SizeX_mm: 3.2; SizeY_mm: 1.6; SizeZ_mm: 1.8; AEC Category: Q200
C33 C38 = GRT188C81A106ME13D: CAP, CERM, 10 µF, 10 V, +/- 20%, X6S, AEC-Q200 Grade 2, 0603; Manufacturer: MuRata; Polarized: N; CompType: Capacitor; Value: 10uF; U/M: EA; Cap_F: 0.00001; Tolerance_%: 20; Value1: Unknown; VDC_V: 10; Value2: 10V; TaMin_C: -55; TaMax_C: 105; SizeArea_mm2: 1.28; SizeAreaWB_mm2: 4.68; SizeX_mm: 1.6; SizeY_mm: 0.8; SizeZ_mm: 1; AEC Category: Q200; AEC Qualified: Y; AEC Grade: 2
C34 C41 = C2012X7R1H225K125AC: as C4 on sheet TIDA-01415_Page1
C37 = GCM188R71E473KA37D: CAP, CERM, 0.047 µF, 25 V, +/- 10%, X7R, AEC-Q200 Grade 1, 0603; Manufacturer: MuRata; Polarized: N; CompType: Capacitor; Value: 0.047uF; U/M: EA; Cap_F: 0.000000047; Tolerance_%: 10; Value1: Unknown; VDC_V: 25; Value2: 25V; TaMin_C: -55; TaMax_C: 125; SizeArea_mm2: 1.28; SizeAreaWB_mm2: 4.68; SizeX_mm: 1.6; SizeY_mm: 0.8; SizeZ_mm: 1; AEC Category: Q200; AEC Qualified: Y
C39 = GRM188R71E104KA01D: CAP, CERM, 0.1 µF, 25 V, +/- 10%, X7R, 0603; Manufacturer: MuRata; Polarized: N; CompType: Capacitor; Value: 0.1uF; U/M: EA; Cap_F: 0.0000001; Tolerance_%: 10; Value1: Unknown; VDC_V: 25; Value2: 25V; TaMin_C: -55; TaMax_C: 125; SizeArea_mm2: 1.28; SizeAreaWB_mm2: 4.68; SizeX_mm: 1.6; SizeY_mm: 0.8; SizeZ_mm: 1; AEC Category: Q200
C40 = CGA4J1X7S1C106K125AC: CAP, CERM, 10 µF, 16 V, +/- 10%, X7S, AEC-Q200 Grade 1, 0805; Manufacturer: TDK; Polarized: N; CompType: Capacitor; Value: 10uF; U/M: EA; Cap_F: 0.00001; Tolerance_%: 10; Value1: Unknown; VDC_V: 16; Value2: 16V; TaMin_C: -55; TaMax_C: 125; Cap_Case: 0805; SizeArea_mm2: 2.5; SizeAreaWB_mm2: 6.75; SizeX_mm: 2; SizeY_mm: 1.25; SizeZ_mm: 1.45; AEC Category: Q200; AEC Qualified: Y; AEC Grade: 1
C42 = GRM155R71C563KA88D: CAP, CERM, 0.056 µF, 16 V, +/- 10%, X7R, 0402; Manufacturer: MuRata; Polarized: N; CompType: Capacitor; Value: 0.056uF; U/M: EA; Cap_F: 0.000000056; Tolerance_%: 10; Value1: Unknown; VDC_V: 16; Value2: 16V; TaMin_C: -55; TaMax_C: 125; SizeArea_mm2: 0.5; SizeAreaWB_mm2: 3; SizeX_mm: 1; SizeZ_mm: 0.6; AEC Category: Q200
C85-C88 = C2012X7R1H104K085AA: as C1 on sheet TIDA-01415_Page1
D7 = MBR1H100SFT3G: Diode, Schottky, 100 V, 1 A, SOD-123FL; Manufacturer: ON Semiconductor; U/M: EA; Vf_V: 0.76; Value: 100V; Value1: 1A; Value2: 0.76V; Io_A: 1; Vr_V: 100; TJmax_C: 175; RJC_CperW: 85; SizeAreaWB_mm2: 12.19; SizeArea_mm2: 5.94; SizeX_mm: 3.6; SizeY_mm: 1.65; SizeZ_mm: 0.98; AEC Category: Q101
GND#1 GND#2 SW5 SW6 TP1 TP3 = 5015: as GLED+ on sheet TIDA-01415_Page1
J1 J3 J6 J8 J12 = 0022284033: Header, 2.54mm, 3x1, Tin, TH; Manufacturer: Molex; SymbolCreator: a0799628; Pitch_mm: 2.54; Gender: Male; Shrouded: N; Row_Count: 1; Current_A: 4; Voltage_V: 250; Cert_UL: Y
L3 = 744053150: Inductor, Shielded Drum Core, Ferrite, 15 µH, 1.15 A, 0.07 ohm, SMD; Manufacturer: Wurth Elektronik; Value: 15uH; Ind_H: 15.0E-6; Imax_A: 1.15; Irms: 1.38A @ 30C rise; Isat: 1.15A @ 35% inductance drop; DCR_ohm: 0.07; Value2: 1.15A; SizeAreaWB_mm2: 60.84; SizeArea_mm2: 33.64; SizeX_mm: 5.8; SizeZ_mm: 2.8; AEC Category: Q200
L4 L5 L10 = 742792662: Ferrite Bead, 1000 ohm @ 100 MHz, 0.6 A, 0603; Manufacturer: Wurth Elektronik; Imax_A: 0.6; DCR_ohm: 0.3; Value1: 0.3 ohm; Value2: 0.6A; ZTyp@100MHz_Ohm: 1000
L6 = BLM15AG221SN1D: Ferrite Bead, 220 ohm @ 100 MHz, 0.45 A, 0402; Manufacturer: MuRata; Value: 220 ohm; Imax_A: 0.45; DCR_ohm: 0.29; Value1: 0.29 ohm; Value2: 0.45A; SizeAreaWB_mm2: 3; SizeArea_mm2: 0.5; SizeX_mm: 1; SizeZ_mm: 0.6; ZTyp@100MHz_Ohm: 220
L7 = SDR0403-331KL: Inductor, Drum Core, Ferrite, 330 µH, 0.17 A, 6 ohm, SMD; Manufacturer: Bourns; Value: 330uH; Ind_H: 330.0E-6; Imax_A: 0.17; Irms: 0.17A @ 40C rise; Isat: 0.25A @ 10% inductance drop; DCR_ohm: 6; Value1: 6 ohm; Value2: 0.17A; SizeAreaWB_mm2: 27.5; SizeArea_mm2: 18; SizeX_mm: 4.5; SizeY_mm: 4; SizeZ_mm: 3.2; AEC Category: Q200
R12 R25 R30 R33 R49 R61 = CRCW0603110KFKEA: RES, 110 k, 1%, 0.1 W, 0603; Manufacturer: Vishay-Dale; CompType: Resistor; Value: 110k; Res_ohm: 110000; Tolerance_%: 1; Power_W: 0.1; Value2: 0.1W; VDC_V: 75; TempCo: 100 ppm/C; SizeArea_mm2: 1.28; SizeX_mm: 1.6; SizeY_mm: 0.8; EIA_Code: E96; U/M: EA; AEC Category: Q200
R14 R28 R52 R64 = CRCW060314K0FKEA: RES, 14.0 k, 1%, 0.1 W, 0603; Manufacturer: Vishay-Dale; CompType: Resistor; Value: 14.0k; Res_ohm: 14000; Value_Code: 14k0; Tolerance_%: 1; Power_W: 0.1; Value2: 0.1W; VDC_V: 75; TempCo: 100 ppm/C; SizeArea_mm2: 1.28; SizeX_mm: 1.6; SizeY_mm: 0.8; EIA_Code: E96; U/M: EA; AEC Category: Q200
R29 = CRCW0603100KFKEA: as R86 on sheet TIDA-01415_Page1
R31 = RC0603FR-0730KL: RES, 30.0 k, 1%, 0.1 W, 0603; Manufacturer: Yageo America; CompType: Resistor; Value: 30.0k; Res_ohm: 30000; Value_Code: 30k0; Tolerance_%: 1; Power_W: 0.1; Value2: 0.1W; VDC_V: 150; TempCo: 200 ppm/C; SizeArea_mm2: 1.28; SizeX_mm: 1.6; SizeY_mm: 0.8; U/M: EA; AEC Category: Q200
R32 = RC0603FR-07100RL: as R94 on sheet TIDA-01415_Page1
R34 = CRCW0402887KFKED: RES, 887 k, 1%, 0.063 W, 0402; Manufacturer: Vishay-Dale; CompType: Resistor; Value: 887k; Res_ohm: 887000; Tolerance_%: 1; Power_W: 0.063; Value2: 0.063W; VDC_V: 50; TempCo: 100 ppm/C; SizeArea_mm2: 0.5; SizeZ_mm: 0.6; EIA_Code: E96; U/M: EA; AEC Category: Q200
R35 = RC0603FR-071K5L: RES, 1.50 k, 1%, 0.1 W, 0603; Manufacturer: Yageo America; CompType: Resistor; Value: 1.50k; Res_ohm: 1500; Value_Code: 1k50; Tolerance_%: 1; Power_W: 0.1; Value2: 0.1W; VDC_V: 150; TempCo: 200 ppm/C; SizeArea_mm2: 1.28; SizeX_mm: 1.6; SizeY_mm: 0.8; EIA_Code: E96; U/M: EA; AEC Category: Q200
R36 = CRCW060312K4FKEA: RES, 12.4 k, 1%, 0.1 W, 0603; Manufacturer: Vishay-Dale; CompType: Resistor; Value: 12.4k; Res_ohm: 12400; Value_Code: 12k4; Tolerance_%: 1; Power_W: 0.1; Value2: 0.1W; VDC_V: 75; TempCo: 100 ppm/C; SizeArea_mm2: 1.28; SizeX_mm: 1.6; SizeY_mm: 0.8; EIA_Code: E96; U/M: EA; AEC Category: Q200
R37 = CRCW0402124KFKED: RES, 124 k, 1%, 0.063 W, 0402; Manufacturer: Vishay-Dale; CompType: Resistor; Value: 124k; Res_ohm: 124000; Tolerance_%: 1; Power_W: 0.063; Value2: 0.063W; VDC_V: 50; TempCo: 100 ppm/C; SizeArea_mm2: 0.5; SizeZ_mm: 0.6; EIA_Code: E96; U/M: EA; AEC Category: Q200
R38 = CRCW0402182KFKED: RES, 182 k, 1%, 0.063 W, 0402; Manufacturer: Vishay-Dale; CompType: Resistor; Value: 182k; Res_ohm: 182000; Tolerance_%: 1; Power_W: 0.063; Value2: 0.063W; VDC_V: 50; TempCo: 100 ppm/C; SizeArea_mm2: 0.5; SizeZ_mm: 0.6; EIA_Code: E96; U/M: EA; AEC Category: Q200
R81 = CRCW1206412RFKEA: RES, 412, 1%, 0.25 W, 1206; Manufacturer: Vishay-Dale; CompType: Resistor; Value: 412; Value_Code: 412R; Tolerance_%: 1; Power_W: 0.25; Value2: 0.25W; VDC_V: 200; TempCo: 100 ppm/C; SizeArea_mm2: 5.12; SizeX_mm: 3.2; SizeY_mm: 1.6; SizeZ_mm: 1.35; EIA_Code: E96; U/M: EA; AEC Category: Q200
SH-J3-SH-J6 = 969102-0000-DA: Shunt, 100mil, Gold plated, Black; Manufacturer: 3M; Alternate Manufacturer: Samtec; Value: 1x2; Note: You can "mate" this to a header by matching the designator.  i.e. use SH-J3 for header J3
U7 = LP5907SNX-3.3/NOPB: 250-mA Ultra-Low-Noise, Low-IQ LDO, DQN0004A (X2SON-4); Manufacturer: Texas Instruments; SymbolCreator: Altium; SizeArea_mm2: 1; SizeAreaWB_mm2: 4; SizeZ_mm: 0.4; CompType: IC; U/M: EA
U8 = LMR16006XDDCR: Wide Input Voltage Range Buck Regulator with High Efficiency Sleep Mode, DDC0006A (SOT-6); Alternate PartNumber: LMR16006XDDCT; Manufacturer: Texas Instruments; SymbolCreator: x0208326; SizeArea_mm2: 4.8675; SizeAreaWB_mm2: 10.4675; SizeX_mm: 1.65; SizeY_mm: 2.95; SizeZ_mm: 0.87; CompType: IC; U/M: EA
U9 = LM5165DRCR: 3V-65V, 150mA Synchronous Buck Converter With Ultra-Low IQ, DRC0010J (VSON-10); Alternate PartNumber: LM5165DRCT; Manufacturer: Texas Instruments; SymbolCreator: Altium; SizeArea_mm2: 9; SizeAreaWB_mm2: 16; SizeX_mm: 3; SizeZ_mm: 1; CompType: IC; U/M: EA

## Sheet TIDA-01415_Page2.SchDoc
size 431 x 279 mm; Date: Not shown in title block; ApprovedBy: Not shown in title block; CheckedBy: Not shown in title block; Author: Not shown in title block; CompanyName: Not shown in title block; Engineer: Not shown in title block; Organization: Not shown in title block; Address1: Not shown in title block; Address2: Not shown in title block; Address3: Not shown in title block; Address4: Not shown in title block; DocumentNumber: 1; Revision: Use project parameter SCH_Rev; SheetNumber: 3; SheetTotal: 6; PageSetup: Record=PageOptions¦CenterHorizontal=True¦CenterVertical=True¦PrintScale=1.00¦XCorrection=1.00¦YCorrection=1.00¦PrintKind=0¦BorderSize=5000000¦LeftOffset=0¦BottomOffset=0¦Orientation=2¦PaperLength=1000¦PaperWidth=1000¦Scale=100¦PaperSource=15¦PrintQuality=600¦MediaType=1¦DitherType=10¦PaperKind=Letter¦PrintScaleMode=1
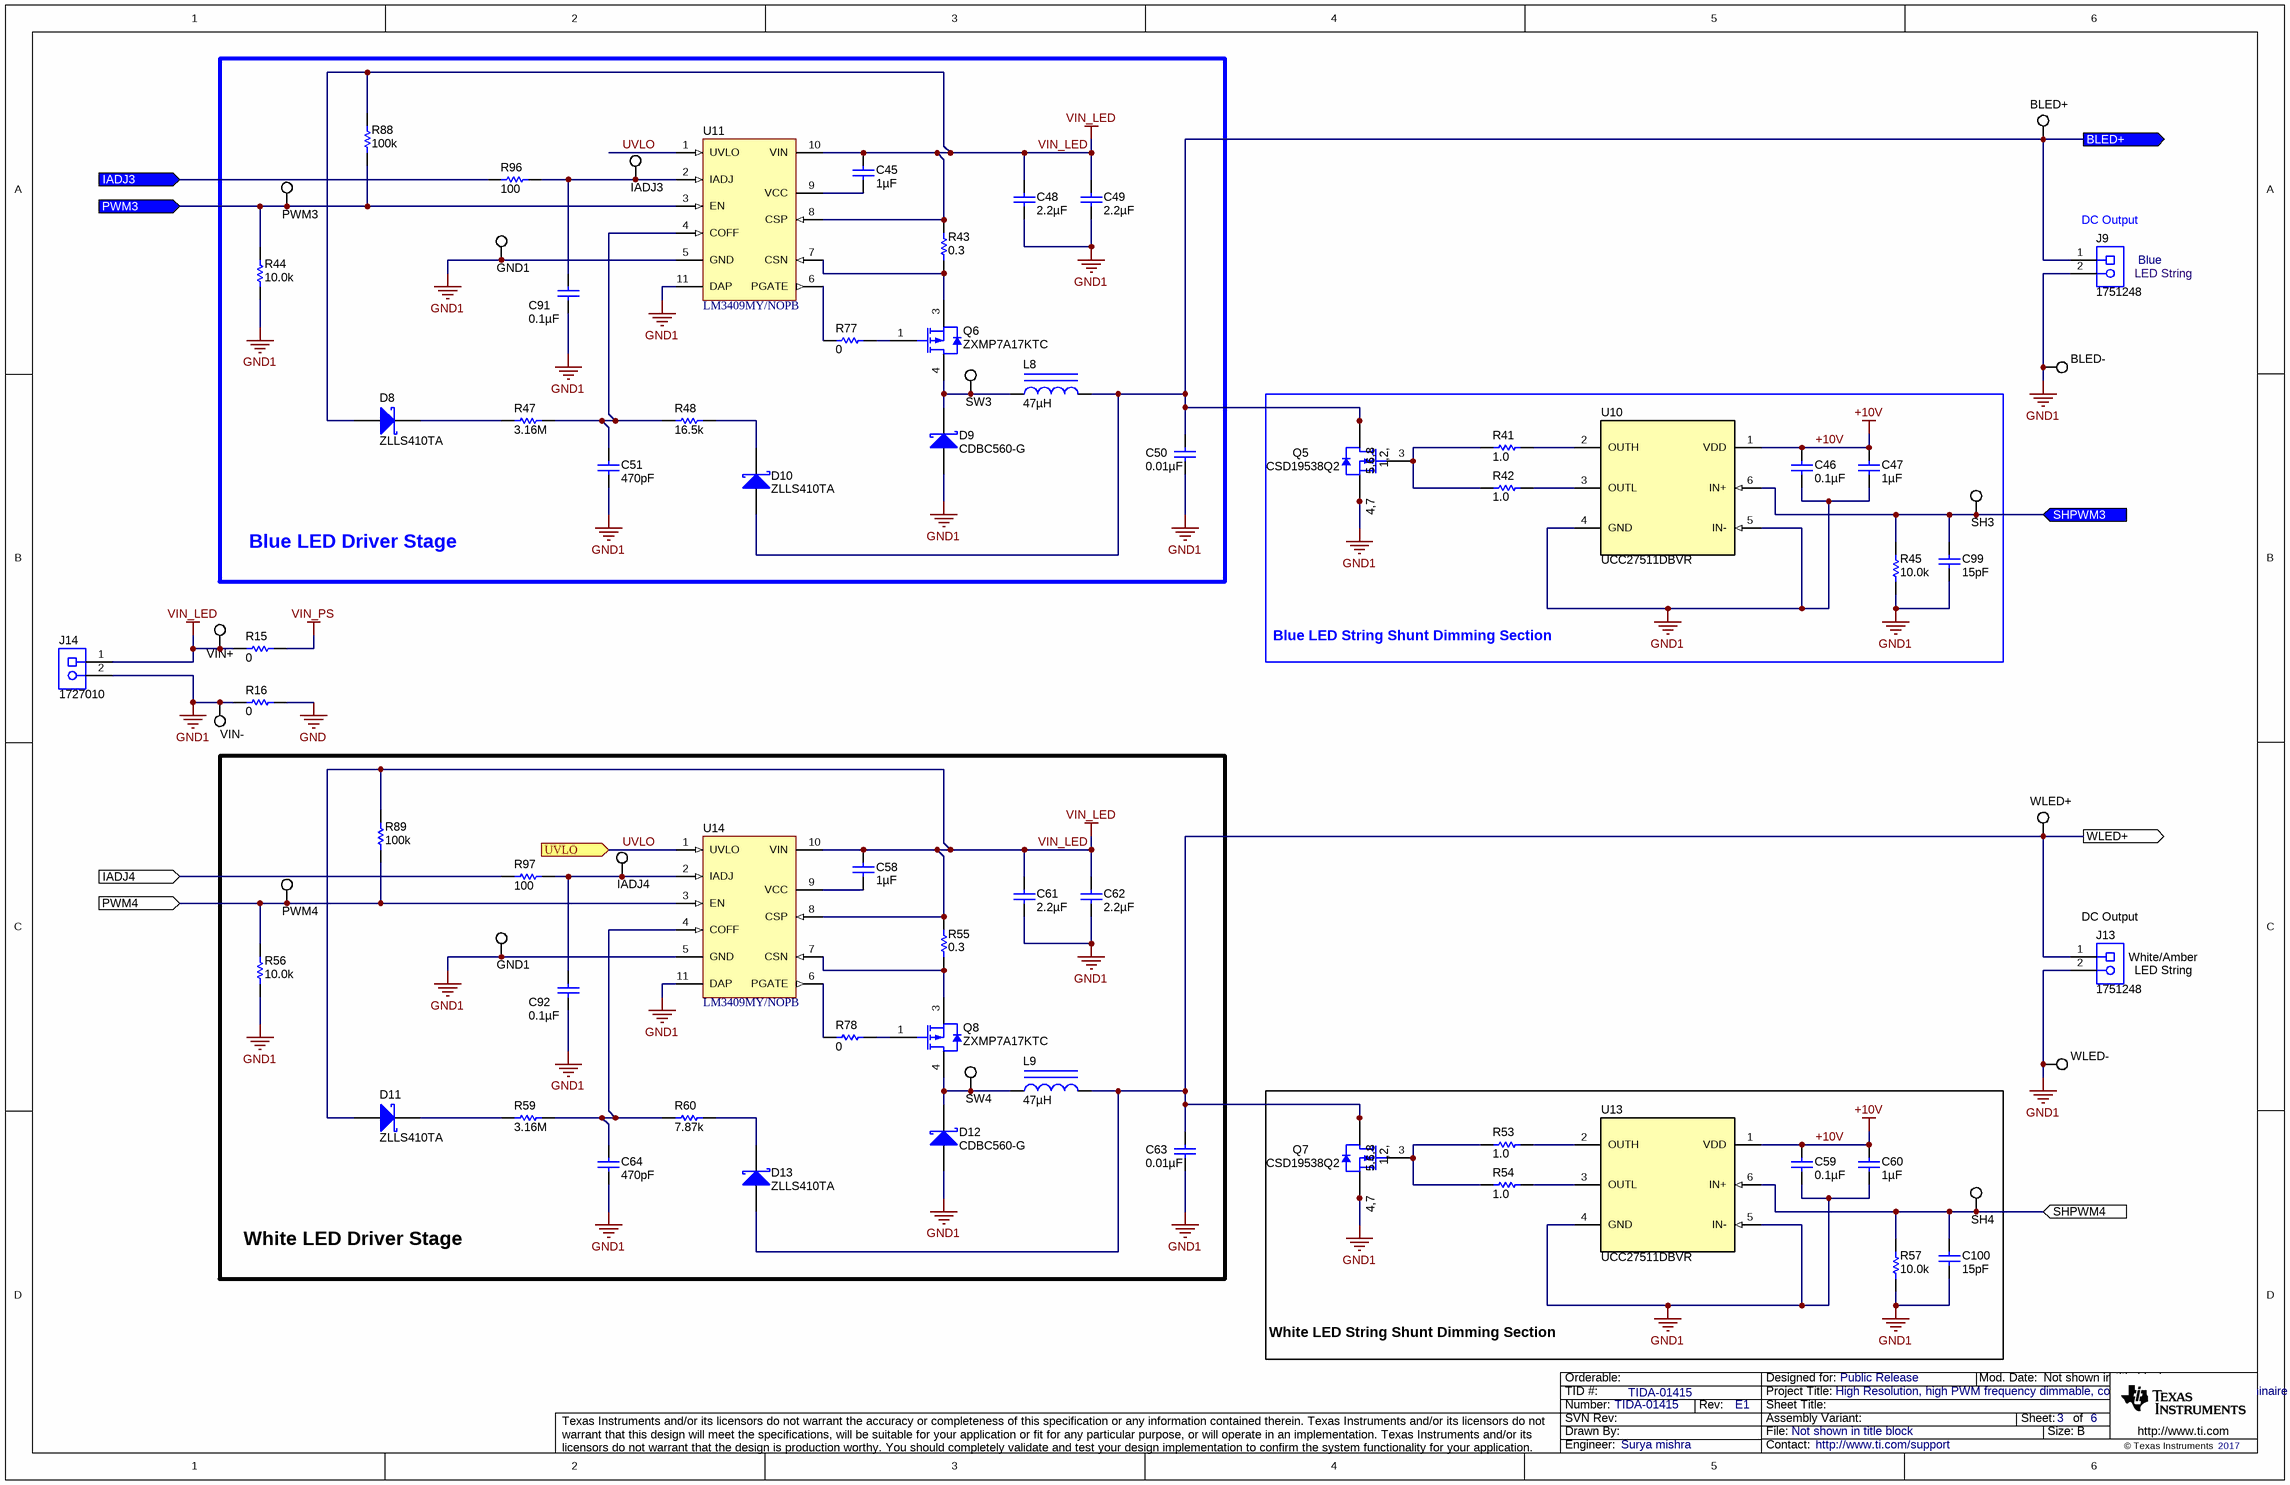
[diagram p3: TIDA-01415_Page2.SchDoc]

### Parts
(Parts that share a designator on the sheet are numbered #1, #2 ... from top to bottom, then left to right.)
BLED+  5015  [Testpoint_Keystone_Miniature]  (value not drawn)
BLED-  5015  [Testpoint_Keystone_Miniature]  (value not drawn)
C45  ValueDisplayed: 1µF  [0603]  (hidden comment: C1608X7R1C105K080AC)
C46  ValueDisplayed: 0.1µF  [0805_HV]  (hidden comment: C2012X7R1H104K085AA)
C47  ValueDisplayed: 1µF  [0805_HV]  (hidden comment: C2012X7R1H105K125AB)
C48  ValueDisplayed: 2.2µF  [0805_HV]  (hidden comment: C2012X7R1H225K125AC)
C49  ValueDisplayed: 2.2µF  [0805_HV]  (hidden comment: C2012X7R1H225K125AC)
C50  ValueDisplayed: 0.01µF  [0805_HV]  (hidden comment: 885012207092)
C51  ValueDisplayed: 470pF  [0201_033]  (hidden comment: CGA1A2X7R1H471K030BA)
C58  ValueDisplayed: 1µF  [0603]  (hidden comment: C1608X7R1C105K080AC)
C59  ValueDisplayed: 0.1µF  [0805_HV]  (hidden comment: C2012X7R1H104K085AA)
C60  ValueDisplayed: 1µF  [0805_HV]  (hidden comment: C2012X7R1H105K125AB)
C61  ValueDisplayed: 2.2µF  [0805_HV]  (hidden comment: C2012X7R1H225K125AC)
C62  ValueDisplayed: 2.2µF  [0805_HV]  (hidden comment: C2012X7R1H225K125AC)
C63  ValueDisplayed: 0.01µF  [0805_HV]  (hidden comment: 885012207092)
C64  ValueDisplayed: 470pF  [0201_033]  (hidden comment: CGA1A2X7R1H471K030BA)
C91  ValueDisplayed: 0.1µF  [0402]  (hidden comment: C1005X7R1E104M050BB)
C92  ValueDisplayed: 0.1µF  [0402]  (hidden comment: C1005X7R1E104M050BB)
C99  ValueDisplayed: 15pF  [0402]  (hidden comment: 885012005056)
C100  ValueDisplayed: 15pF  [0402]  (hidden comment: 885012005056)
D8  ZLLS410TA  [SOD-323]
D9  CDBC560-G  [SMC]
D10  ZLLS410TA  [SOD-323]
D11  ZLLS410TA  [SOD-323]
D12  CDBC560-G  [SMC]
D13  ZLLS410TA  [SOD-323]
GND1#3  5015  [Testpoint_Keystone_Miniature]  (value not drawn)
GND1#4  5015  [Testpoint_Keystone_Miniature]  (value not drawn)
IADJ3  5015  [Testpoint_Keystone_Miniature]  (value not drawn)
IADJ4  5015  [Testpoint_Keystone_Miniature]  (value not drawn)
J9  1751248  [CONN_1751248]
J13  1751248  [CONN_1751248]
J14  1727010  [PhoenixConact_1727010]
L8  ValueDisplayed: 47µH  [WE-PD_1280]  (hidden comment: 744770147)
L9  ValueDisplayed: 47µH  [WE-PD_1280]  (hidden comment: 744770147)
PWM3  5015  [Testpoint_Keystone_Miniature]  (value not drawn)
PWM4  5015  [Testpoint_Keystone_Miniature]  (value not drawn)
Q5  CSD19538Q2  [DQK0006C]
Q6  ZXMP7A17KTC  [DPAK]
Q7  CSD19538Q2  [DQK0006C]
Q8  ZXMP7A17KTC  [DPAK]
R15  ValueDisplayed: 0  [0402]  (hidden comment: CRCW04020000Z0ED)
R16  ValueDisplayed: 0  [0402]  (hidden comment: CRCW04020000Z0ED)
R41  ValueDisplayed: 1.0  [0603]  (hidden comment: CRCW06031R00JNEA)
R42  ValueDisplayed: 1.0  [0603]  (hidden comment: CRCW06031R00JNEA)
R43  ValueDisplayed: 0.3  [2512]  (hidden comment: CSRN2512FKR300)
R44  ValueDisplayed: 10.0k  [0603]  (hidden comment: CRCW060310K0FKEA)
R45  ValueDisplayed: 10.0k  [0603]  (hidden comment: CRCW060310K0FKEA)
R47  ValueDisplayed: 3.16M  [0603]  (hidden comment: CRCW06033M16FKEA)
R48  ValueDisplayed: 16.5k  [0603]  (hidden comment: CRCW060316K5FKEA)
R53  ValueDisplayed: 1.0  [0603]  (hidden comment: CRCW06031R00JNEA)
R54  ValueDisplayed: 1.0  [0603]  (hidden comment: CRCW06031R00JNEA)
R55  ValueDisplayed: 0.3  [2512]  (hidden comment: CSRN2512FKR300)
R56  ValueDisplayed: 10.0k  [0603]  (hidden comment: CRCW060310K0FKEA)
R57  ValueDisplayed: 10.0k  [0603]  (hidden comment: CRCW060310K0FKEA)
R59  ValueDisplayed: 3.16M  [0603]  (hidden comment: CRCW06033M16FKEA)
R60  ValueDisplayed: 7.87k  [0603]  (hidden comment: CRCW06037K87FKEA)
R77  ValueDisplayed: 0  [0603]  (hidden comment: CRCW06030000Z0EA)
R78  ValueDisplayed: 0  [0603]  (hidden comment: CRCW06030000Z0EA)
R88  ValueDisplayed: 100k  [0603]  (hidden comment: CRCW0603100KFKEA)
R89  ValueDisplayed: 100k  [0603]  (hidden comment: CRCW0603100KFKEA)
R96  ValueDisplayed: 100  [0603]  (hidden comment: RC0603FR-07100RL)
R97  ValueDisplayed: 100  [0603]  (hidden comment: RC0603FR-07100RL)
SH3  5015  [Testpoint_Keystone_Miniature]  (value not drawn)
SH4  5015  [Testpoint_Keystone_Miniature]  (value not drawn)
SW3  5015  [Testpoint_Keystone_Miniature]  (value not drawn)
SW4  5015  [Testpoint_Keystone_Miniature]  (value not drawn)
U10  UCC27511DBVR  [DBV0006A_N]
U11  LM3409MY/NOPB  [MUC10A_N]
U13  UCC27511DBVR  [DBV0006A_N]
U14  LM3409MY/NOPB  [MUC10A_N]
VIN+  5015  [Testpoint_Keystone_Miniature]  (value not drawn)
VIN-  5015  [Testpoint_Keystone_Miniature]  (value not drawn)
WLED+  5015  [Testpoint_Keystone_Miniature]  (value not drawn)
WLED-  5015  [Testpoint_Keystone_Miniature]  (value not drawn)

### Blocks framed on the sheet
Blue LED Driver Stage: C45 C48-C51 C91 D8-D10 GND1#3 IADJ3 L8 PWM3 Q6 R43 R44 R47 R48 R77 R88 R96 SW3 U11
Blue LED String Shunt Dimming Section: C46 C47 C99 Q5 R41 R42 R45 SH3 U10
White LED Driver Stage: C58 C61-C64 C92 D11-D13 GND1#4 IADJ4 L9 PWM4 Q8 R55 R56 R59 R60 R78 R89 R97 SW4 U14
White LED String Shunt Dimming Section: C59 C60 C100 Q7 R53 R54 R57 SH4 U13

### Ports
BLED+ (out), IADJ3 (in), IADJ4 (in), PWM3 (in), PWM4 (in), SHPWM3 (in), SHPWM4 (in), UVLO (in), WLED+ (out)

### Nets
+10V: C46.1 C47.1 C59.1 C60.1 U10.1(VDD) U13.1(VDD)
GND: R16.2
GND1: BLED-.1 C46.2 C47.2 C48.2 C49.2 C50.2 C51.2 C59.2 C60.2 C61.2 C62.2 C63.2 C64.2 C91.1 C92.1 C99.2 C100.2 D9.2(A) D12.2(A) GND1#3.1 GND1#4.1 J9.2 J13.2 J14.2 Q5.4(S) Q5.7(S) Q7.4(S) Q7.7(S) R16.1 R44.1 R45.1 R56.1 R57.1 U10.4(GND) U10.5(IN-) U11.5(GND) U11.11(DAP) U13.4(GND) U13.5(IN-) U14.5(GND) U14.11(DAP) VIN-.1 WLED-.1
VIN_LED: C45.1 C48.1 C49.1 C58.1 C61.1 C62.1 D8.2(A) D11.2(A) J14.1 R15.1 R43.2 R55.2 R88.2 R89.2 U11.8(CSP) U11.10(VIN) U14.8(CSP) U14.10(VIN) VIN+.1
VIN_PS: R15.2
BLED+: BLED+.1 C50.1 D10.2(A) J9.1 L8.2 Q5.1(D) Q5.2(D) Q5.5(D) Q5.6(D) Q5.8(D) ; port BLED+
IADJ3: R96.2 ; port IADJ3
IADJ4: R97.2 ; port IADJ4
PWM3: PWM3.1 R44.2 R88.1 U11.3(EN) ; port PWM3
PWM4: PWM4.1 R56.2 R89.1 U14.3(EN) ; port PWM4
SHPWM3: C99.1 R45.2 SH3.1 U10.6(IN+) ; port SHPWM3
SHPWM4: C100.1 R57.2 SH4.1 U13.6(IN+) ; port SHPWM4
UVLO: U11.1(UVLO) U14.1(UVLO) ; port UVLO
WLED+: C63.1 D13.2(A) J13.1 L9.2 Q7.1(D) Q7.2(D) Q7.5(D) Q7.6(D) Q7.8(D) WLED+.1 ; port WLED+
NetC45_2: C45.2 U11.9(VCC)
NetC51_1: C51.1 R47.2 R48.1 U11.4(COFF)
NetC58_2: C58.2 U14.9(VCC)
NetC64_1: C64.1 R59.2 R60.1 U14.4(COFF)
NetC91_2: C91.2 IADJ3.1 R96.1 U11.2(IADJ)
NetC92_2: C92.2 IADJ4.1 R97.1 U14.2(IADJ)
NetD8_1: D8.1(K) R47.1
NetD9_1: D9.1(K) L8.1 Q6.4(D) SW3.1
NetD10_1: D10.1(K) R48.2
NetD11_1: D11.1(K) R59.1
NetD12_1: D12.1(K) L9.1 Q8.4(D) SW4.1
NetD13_1: D13.1(K) R60.2
NetQ5_3: Q5.3(G) R41.1 R42.1
NetQ6_1: Q6.1(G) R77.2
NetQ6_3: Q6.3(S) R43.1 U11.7(CSN)
NetQ7_3: Q7.3(G) R53.1 R54.1
NetQ8_1: Q8.1(G) R78.2
NetQ8_3: Q8.3(S) R55.1 U14.7(CSN)
NetR41_2: R41.2 U10.2(OUTH)
NetR42_2: R42.2 U10.3(OUTL)
NetR53_2: R53.2 U13.2(OUTH)
NetR54_2: R54.2 U13.3(OUTL)
NetR77_1: R77.1 U11.6(PGATE)
NetR78_1: R78.1 U14.6(PGATE)

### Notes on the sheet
- (near J9) DC Output
- (near J9) Blue
- (near J9) LED String
- (near J13) DC Output
- (near J13) White/Amber
- (near J13) LED String

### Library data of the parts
BLED+ BLED- GND1#3 GND1#4 IADJ3 IADJ4 PWM3 PWM4 SH3 SH4 SW3 SW4 VIN+ VIN- WLED+ WLED- = 5015: as GLED+ on sheet TIDA-01415_Page1
C45 C58 = C1608X7R1C105K080AC: as C3 on sheet TIDA-01415_Page1
C46 C59 = C2012X7R1H104K085AA: as C1 on sheet TIDA-01415_Page1
C47 C60 = C2012X7R1H105K125AB: as C2 on sheet TIDA-01415_Page1
C48 C49 C61 C62 = C2012X7R1H225K125AC: as C4 on sheet TIDA-01415_Page1
C50 C63 = 885012207092: as C6 on sheet TIDA-01415_Page1
C51 C64 = CGA1A2X7R1H471K030BA: as C7 on sheet TIDA-01415_Page1
C91 C92 = C1005X7R1E104M050BB: as C89 on sheet TIDA-01415_Page1
C99 C100 = 885012005056: as C97 on sheet TIDA-01415_Page1
D8 D10 D11 D13 = ZLLS410TA: as D1 on sheet TIDA-01415_Page1
D9 D12 = CDBC560-G: as D2 on sheet TIDA-01415_Page1
J9 J13 = 1751248: as J2 on sheet TIDA-01415_Page1
J14 = 1727010: Conn Term Block, 2POS, 3.81mm, TH; Manufacturer: Phoenix Contact; SymbolCreator: a0412235; CompType: Terminal Block
L8 L9 = 744770147: as L1 on sheet TIDA-01415_Page1
Q5 Q7 = CSD19538Q2: as Q1 on sheet TIDA-01415_Page1
Q6 Q8 = ZXMP7A17KTC: as Q2 on sheet TIDA-01415_Page1
R15 R16 = CRCW04020000Z0ED: RES, 0, 5%, 0.063 W, 0402; Manufacturer: Vishay-Dale; CompType: Resistor; Value: 0; Value_Code: 0000; Tolerance_%: 5; Power_W: 0.063; Value2: 0.063W; VDC_V: 50; TempCo: 200 ppm/C; SizeArea_mm2: 0.5; SizeX_mm: 1; SizeZ_mm: 0.6; EIA_Code: E24; U/M: EA; AEC Category: Q200
R41 R42 R53 R54 = CRCW06031R00JNEA: as R3 on sheet TIDA-01415_Page1
R43 R55 = CSRN2512FKR300: as R5 on sheet TIDA-01415_Page1
R44 R45 R56 R57 = CRCW060310K0FKEA: as R6 on sheet TIDA-01415_Page1
R47 R59 = CRCW06033M16FKEA: as R9 on sheet TIDA-01415_Page1
R48 = CRCW060316K5FKEA: as R10 on sheet TIDA-01415_Page1
R60 = CRCW06037K87FKEA: RES, 7.87 k, 1%, 0.1 W, 0603; Manufacturer: Vishay-Dale; CompType: Resistor; Value: 7.87k; Res_ohm: 7870; Value_Code: 7k87; Tolerance_%: 1; Power_W: 0.1; Value2: 0.1W; VDC_V: 75; TempCo: 100 ppm/C; SizeArea_mm2: 1.28; SizeX_mm: 1.6; SizeY_mm: 0.8; EIA_Code: E96; U/M: EA; AEC Category: Q200
R77 R78 = CRCW06030000Z0EA: as R75 on sheet TIDA-01415_Page1
R88 R89 = CRCW0603100KFKEA: as R86 on sheet TIDA-01415_Page1
R96 R97 = RC0603FR-07100RL: as R94 on sheet TIDA-01415_Page1
U10 U13 = UCC27511DBVR: as U1 on sheet TIDA-01415_Page1
U11 U14 = LM3409MY/NOPB: as U2 on sheet TIDA-01415_Page1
